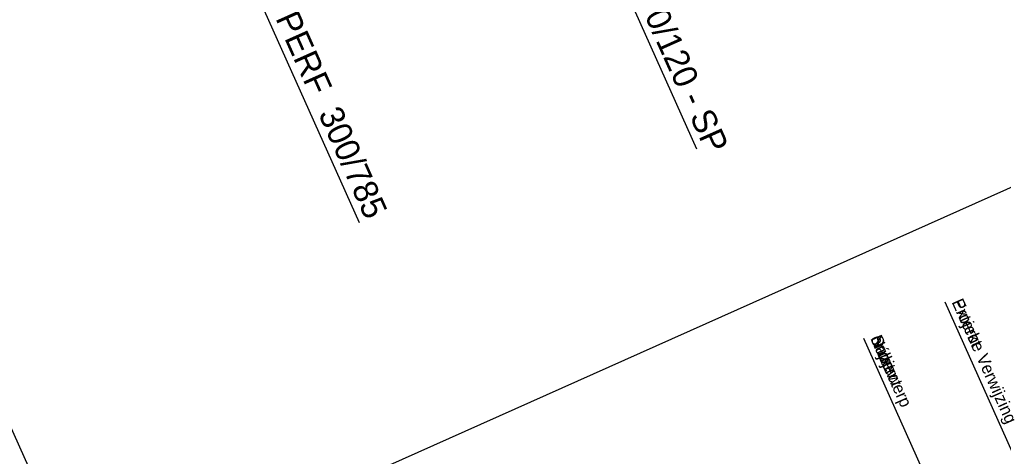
# Model space of a CAD drawing. Extents: x -781656 to -760591, y -1008106 to -975620.
# Drawn here: x -781653.865 to -781651.438, y -1008101.302 to -1008100.224 of the extents above; entities that cross this region are included whole.
import ezdxf

# ---------------------------------------------------------------- set-up
doc = ezdxf.new("R2010")
doc.units = 0
for name, color, linetype in [('Border', 7, 'Continuous'), ('Border_TextCZ', 7, 'Continuous'), ('Border_TextFR', 7, 'Continuous'), ('Border_TextNL', 7, 'Continuous'), ('Border_TextUK', 7, 'Continuous'), ('Implicitní', 7, 'Continuous')]:
    doc.layers.add(name, color=color, linetype=linetype)

# ---------------------------------------------------------------- blocks, each defined once
blk = doc.blocks.new('A3coversheet_v03_CZ_1_1')
at = {"layer": 'Border'}
for points in [[(2.1, 0), (2.1, 2.97), (4.2, 2.97)], [(2.1, 0.07), (0.2, 0.07), (0.2, 2.91), (2.1, 2.91)], [(2.1958, 1.185), (4.1042, 1.185)], [(2.1958, 1.075), (4.1042, 1.075)]]:
    blk.add_lwpolyline(points, dxfattribs=at)
at = {"layer": 'Border_TextCZ'}
for s, p in [('Projekt', (2.1994, 1.1922)), ('Název', (2.1994, 1.0822))]:
    blk.add_text(s, height=0.015, dxfattribs=at).set_placement(p)
at = {"layer": 'Border_TextFR'}
for s, p in [('Projet', (2.1994, 1.1922)), ('Sujet', (2.1994, 1.0822))]:
    blk.add_text(s, height=0.015, dxfattribs=at).set_placement(p)
at = {"layer": 'Border_TextNL'}
for s, p in [('Externe Verwijzing', (2.1994, 1.1922)), ('onderwerp', (2.1994, 1.0822))]:
    blk.add_text(s, height=0.015, dxfattribs=at).set_placement(p)
at = {"layer": 'Border_TextUK'}
for s, p in [('Project', (2.1994, 1.1922)), ('Subject', (2.1994, 1.0822))]:
    blk.add_text(s, height=0.015, dxfattribs=at).set_placement(p)

msp = doc.modelspace()

# ---------------------------------------------------------------- linework, layer by layer
at = {"layer": 'Implicitní'}
for points in [[(-781652.6102, -1008099.1468), (-781652.6245, -1008099.5826), (-781652.195, -1008100.5429)], [(-781653.3731, -1008099.5231), (-781653.3858, -1008099.9232), (-781653.0274, -1008100.7246)]]:
    msp.add_lwpolyline(points, dxfattribs=at)

# ---------------------------------------------------------------- block references
at = {"layer": 'Border', "xscale": 2.0000000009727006, "yscale": 2.0000000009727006, "rotation": -65.8996989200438}
msp.add_blockref('A3coversheet_v03_CZ_1_1', (-781655.5387, -1008097.8791), dxfattribs=at)

# ---------------------------------------------------------------- texts
at = {"layer": 'Implicitní'}
for s, p in [('TBS - Q - 1000/1000/120 - SP', (-781652.6078, -1008099.5784)), ('TBZ - Q  PERF  300/785', (-781653.3691, -1008099.919))]:
    msp.add_text(s, height=0.06, rotation=294.1003, dxfattribs=at).set_placement(p)

doc.saveas('drawing.dxf')
